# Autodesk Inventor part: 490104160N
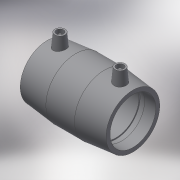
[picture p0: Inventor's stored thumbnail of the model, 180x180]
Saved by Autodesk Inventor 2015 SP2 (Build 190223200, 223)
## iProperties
Created: 2017-06
Part Number: 490104160N
Material: Generic
Description: PLASSON COUPLER 160-160
Document SubType Name: Modeling
Designer: KIM
Mass: 1476.76 g
Surface Area: 2329.18 cm^2
Volume: 1476.76 cm^3
Density: 1 g/cm^3
Appearance: Default
Author: KIM
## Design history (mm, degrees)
derived "490104.ipt"
feature "Solid1::490104.ipt"
tag "TaggingFeature1"
body "Solid1"
other parameters: "d0" = 195, "d2" = 194, "d3" = 93, "d4" = 65, "d5" = 174.6, "d6" = 152, "d8" = 168 deg, "d10" = 37.2, "d11" = 12.4, "d13" = 195, "d14" = 17.6296, "d15" = 93, "d16" = 93, "d17" = 152, "d19" = 3.52592, "d20" = 168 deg, "d22" = 182.36, "d23" = 194, "d24" = 176.8892, "d25" = 135 deg, "d26" = 78, "d27" = 135 deg, "d29" = 105, "d30" = 14, "d31" = 68.25, "d34" = 5 deg, "d35" = 15, "d39" = 5 deg, "d41" = 4, "d42" = 14, "d43" = 0, "d45" = 4, "d46" = 14, "d47" = 0, "d48" = 3, "d49" = 0, "d50" = 3, "d51" = 0, "d52" = 26.97, "d53" = 6.7425, "L_" = 195, "L_1" = 93, "D_" = 194, "A_" = 105, "d_2" = 12
